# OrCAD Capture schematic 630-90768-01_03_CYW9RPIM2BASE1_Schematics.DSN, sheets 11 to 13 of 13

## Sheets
11 11. Power Supply & Accessories: size B
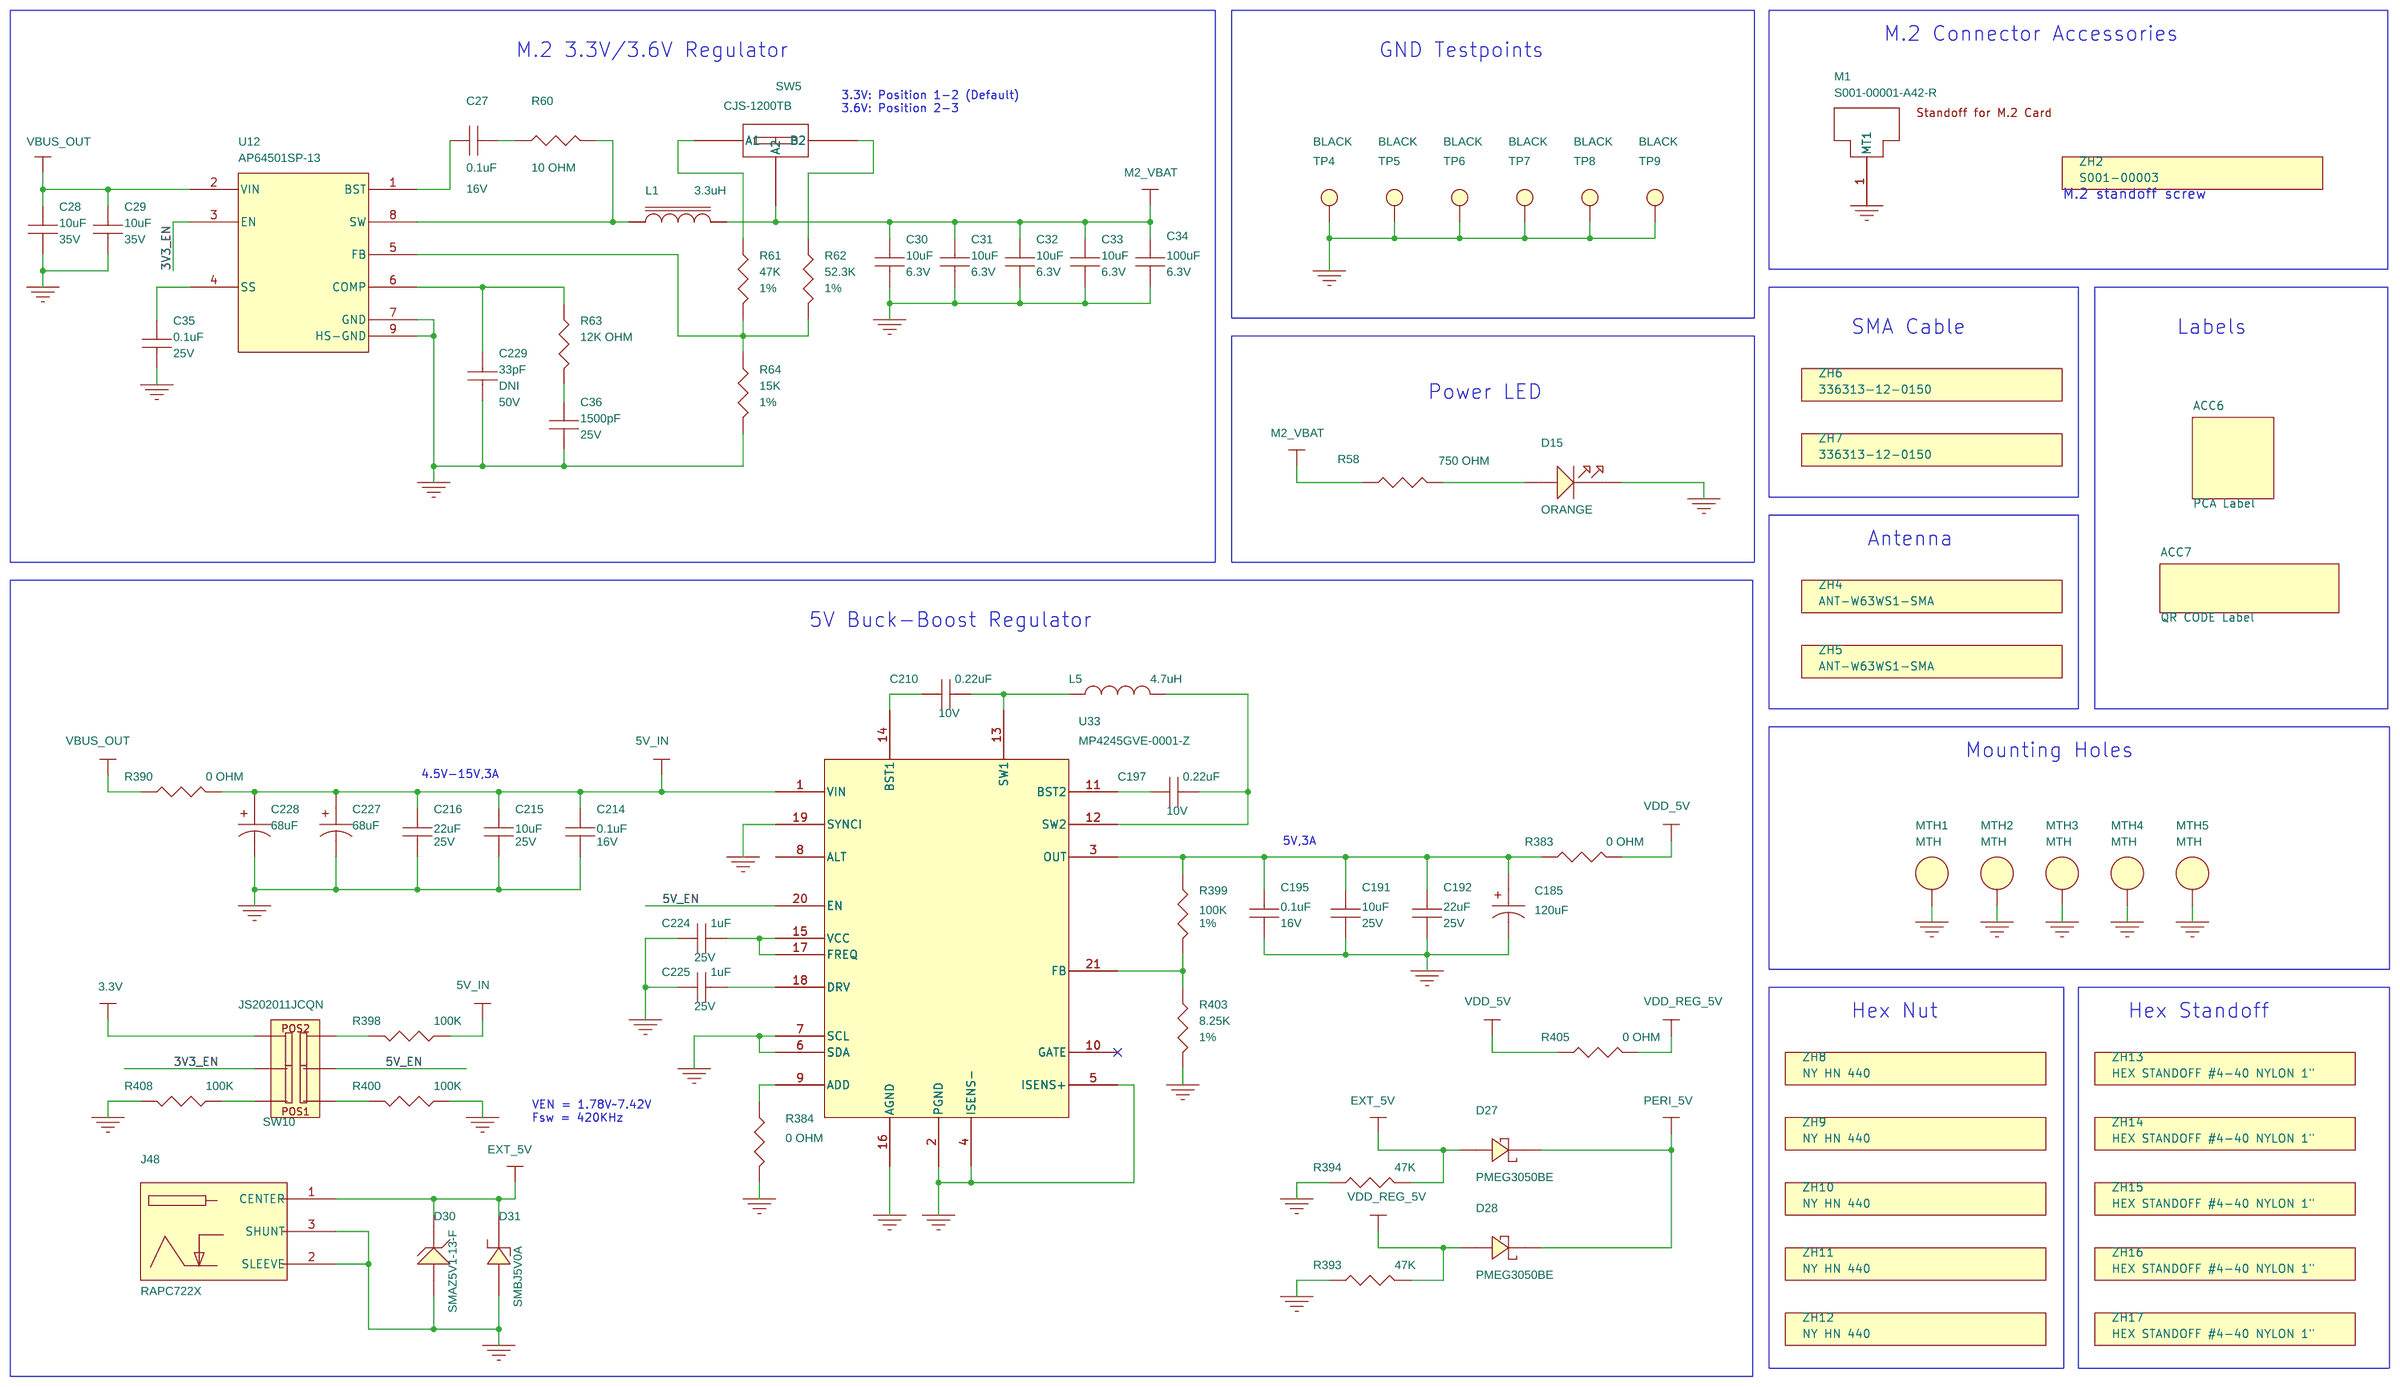
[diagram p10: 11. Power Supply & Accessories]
12 13. Revision History
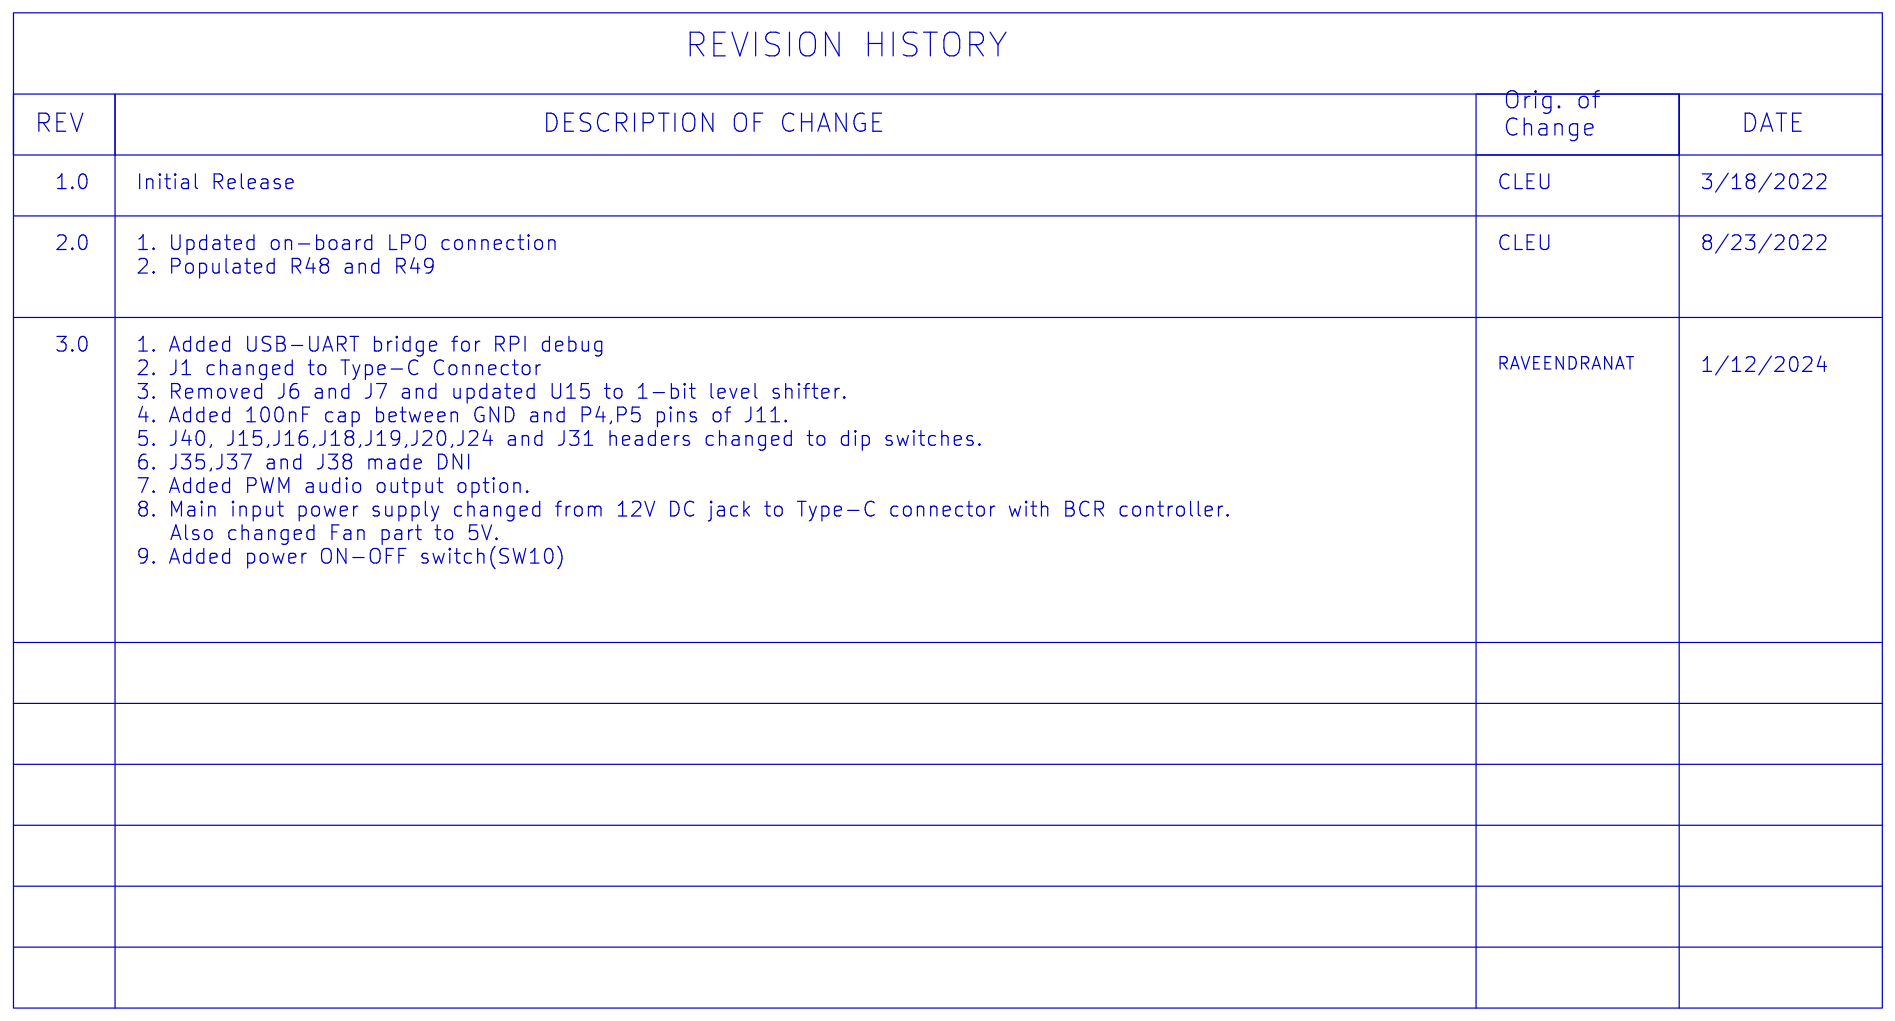
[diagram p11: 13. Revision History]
13 12. GPIO Mappings and Config.
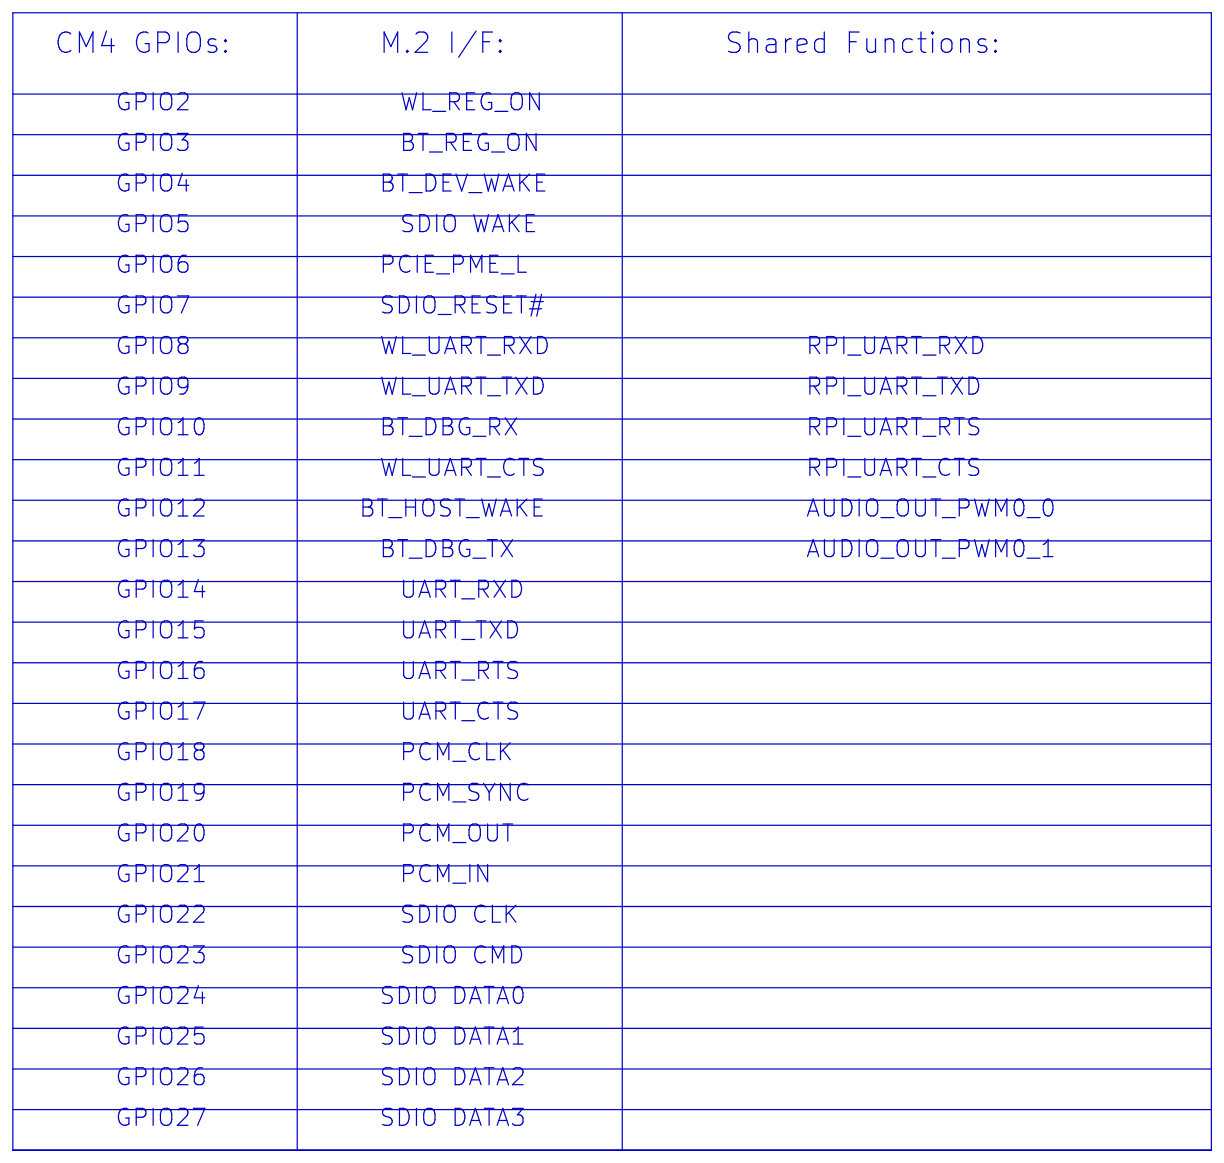
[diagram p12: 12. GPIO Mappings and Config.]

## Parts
ACC6  PCA Label  [TBD]
ACC7  QR CODE Label  [TBD]
C27  0.1uF  [CAPC1005_IS0402Q]
C28  10uF  [CAPC2012_IS0805Q]
C29  10uF  [CAPC2012_IS0805Q]
C30  10uF  [CAPC1005_IS0402Q]
C31  10uF  [CAPC1005_IS0402Q]
C32  10uF  [CAPC1005_IS0402Q]
C33  10uF  [CAPC1005_IS0402Q]
C34  100uF  [CAPC3216_IS1206N]
C35  0.1uF  [CAPC1608_IS0603Q]
C36  1500pF  [CAPC1005_IS0402Q]
C185  120uF  [CAPAE650X600N]
C191  10uF  [CAPC2012_IS0805Q]
C192  22uF  [CAPC2012_IS0805Q]
C195  0.1uF  [CAPC1005_IS0402Q]
C197  0.22uF  [CAPC1005_IS0402Q]
C210  0.22uF  [CAPC1005_IS0402Q]
C214  0.1uF  [CAPC1005_IS0402Q]
C215  10uF  [CAPC2012_IS0805Q]
C216  22uF  [CAPC2012_IS0805Q]
C224  1uF  [CAPC1608_IS0603Q]
C225  1uF  [CAPC1608_IS0603Q]
C227  68uF  [CAPAE650X600N]
C228  68uF  [CAPAE650X600N]
C229  33pF  [CAPC1005_IS0402Q]
D15  ORANGE  [LEDC1608Q]
D27  PMEG3050BE  [SODFL4725X110N]
D28  PMEG3050BE  [SODFL4725X110N]
D30  SMAZ5V1-13-F  [DIOM4326_SMA_DO214ACN]
D31  SMBJ5V0A  [DIOM4336_SMB_DO214AAN]
J48  RAPC722X  [SWCFT_RAPC722]
L1  3.3uH  [inds2_4p7mm_6x6]
L5  4.7uH  [IND_744311470]
M1  S001-00001-A42-R  [MT_pth4_20]
MTH1  MTH  [mtghole_tc650d350p]
MTH2  MTH  [mtghole_tc650d350p]
MTH3  MTH  [mtghole_tc650d350p]
MTH4  MTH  [mtghole_tc650d350p]
MTH5  MTH  [mtghole_tc650d350p]
R58  750 OHM  [RESC1005_IS0402Q]
R60  10 OHM  [RESC1005_IS0402Q]
R61  47K  [RESC1005_IS0402Q]
R62  52.3K  [RESC1005_IS0402Q]
R63  12K OHM  [RESC1005_IS0402Q]
R64  15K  [RESC1005_IS0402Q]
R383  0 OHM  [RESC2012_IS0805Q]
R384  0 OHM  [RESC1005_IS0402Q]
R390  0 OHM  [RESC2012_IS0805Q]
R393  47K  [RESC1005_IS0402Q]
R394  47K  [RESC1005_IS0402Q]
R398  100K  [RESC1005_IS0402Q]
R399  100K  [RESC1005_IS0402Q]
R400  100K  [RESC1005_IS0402Q]
R403  8.25K  [RESC1005_IS0402Q]
R405  0 OHM  [RESC2012_IS0805Q]
R408  100K  [RESC1005_IS0402Q]
SW5  CJS-1200TB  [SWDPS2_CJS]
SW10  JS202011JCQN  [SW_JS202011JCQN]
TP4  BLACK  [TPT1_KOB_151-10X-RC]
TP5  BLACK  [TPT1_KOB_151-10X-RC]
TP6  BLACK  [TPT1_KOB_151-10X-RC]
TP7  BLACK  [TPT1_KOB_151-10X-RC]
TP8  BLACK  [TPT1_KOB_151-10X-RC]
TP9  BLACK  [TPT1_KOB_151-10X-RC]
U12  AP64501SP-13  [so8_p127_490x600]
U33  MP4245GVE-0001-Z  [QFN50P400X500X100-21N_NOFID]
ZH2  S001-00003  [NA]
ZH4  ANT-W63WS1-SMA  [NA]
ZH5  ANT-W63WS1-SMA  [NA]
ZH6  336313-12-0150  [NA]
ZH7  336313-12-0150  [NA]
ZH8  NY HN 440  [NA]
ZH9  NY HN 440  [NA]
ZH10  NY HN 440  [NA]
ZH11  NY HN 440  [NA]
ZH12  NY HN 440  [NA]
ZH13  HEX STANDOFF #4-40 NYLON 1"  [NA]
ZH14  HEX STANDOFF #4-40 NYLON 1"  [NA]
ZH15  HEX STANDOFF #4-40 NYLON 1"  [NA]
ZH16  HEX STANDOFF #4-40 NYLON 1"  [NA]
ZH17  HEX STANDOFF #4-40 NYLON 1"  [NA]

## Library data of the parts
ACC6 = LABEL: LBL, PCA Label, Vendor Code, Datecode, Serial Number (YYWWVVXXXXX); CY_PN: 899-90120-01; Device File: 899-60120-01; HARD_LOCATION: YES; Manufacturer: JETech; Manufacturer_PN: 899-60120-01; Operating_Temp: NA; Part_Status: In Prod
ACC7 = Zero_Pin_Rect: LBL, QR CODE, 10mm X 10mm, CYW9RPIWIFIBT-EVK; CY_PN: 899-90258-01; HARD_LOCATION: YES; Manufacturer: Cypress Approved CM; Manufacturer_PN: NA; Operating_Temp: NA; Part_Status: Unrel
C27 C195 C214 = CAP: CAP, CER, 0402, 0.1uF, 10%, 16V, X7R; Assembly Instructions: <Assembly Instructions>; BRCM PN: 520157-00; CYPN: 510-90749-01; Enviromental: RoHS; FPLIST: CAPC1005_IS0402Q,CAPC1005_IS0402N,capc1005_is0402q_HP; PART TYPE: Ceramic Capacitor; Size: 0402; Status: APPROVED; TC: X7R; Tolerance: 10%; VOLTAGE: 16V; vendor_1: DARFON; vendor_2: DARFON; vendor_3: Walsin; vendor_4: Samsung; vendor_5: Murata Electronics North America; vendor_part_number_1: C1005X7R104KETS; vendor_part_number_2: C1005X7R104KETA; vendor_part_number_3: 0402B104K160CT; vendor_part_number_4: CL05B104KO5NNNC; vendor_part_number_5: GRM155R71C104KA88D -NRND-; Datasheet: \\shasdv005.infineon.com\CMU\CMU_ORCAD_CIS_LIB\CYPRESS_CIS_DATABASE\datasheet\Murata_GRM155R71C104KA88D.pdf
C28 C29 = CAP: CAP, CER, 0805, 10uF, 10%, 35V, X5R; Assembly Instructions: <Assembly Instructions>; CYPN: 510-91233-01; Enviromental: RoHS; FPLIST: CAPC2012_IS0805Q,CAPC2012_IS0805N; PART TYPE: Ceramic Capacitor; Size: 0805; Status: APPROVED; TC: X5R; Tolerance: 10%; VOLTAGE: 35V; vendor_1: Murata; vendor_part_number_1: GRM21BR6YA106KE43L; Datasheet: \\shasdv005.infineon.com\CMU\CMU_ORCAD_CIS_LIB\CYPRESS_CIS_DATABASE\datasheet\GRM21BR6YA106KE43L.pdf
C30-C33 = CAP: CAP, CER, 0402, 10uF, 20%, 6.3V, X5R; Assembly Instructions: <Assembly Instructions>; BRCM PN: 543921-00; CYPN: 510-90758-01; Enviromental: RoHS; FPLIST: CAPC1005_IS0402Q,CAPC1005_IS0402N; PART TYPE: Ceramic Capacitor; Size: 0402; Status: APPROVED; TC: X5R; Tolerance: 20%; VOLTAGE: 6.3V; vendor_1: DARFON; vendor_2: Murata; vendor_3: Murata; vendor_4: Walsin; vendor_part_number_1: C1005X5R106MCTS; vendor_part_number_2: GRM155R60J106ME44D-EOL; vendor_part_number_3: GRM155R60J106ME15D; vendor_part_number_4: 0402X106M6R3CT; Datasheet: \\shasdv005.infineon.com\CMU\CMU_ORCAD_CIS_LIB\CYPRESS_CIS_DATABASE\datasheet\GRM155R60J106ME44D.pdf
C34 = CAP: CAP, CER, 1206, 100uF, 20%, 6.3V, X5R; Assembly Instructions: <Assembly Instructions>; BRCM PN: 537294-00; CYPN: 510-91191-01; Enviromental: RoHS; PART TYPE: Ceramic Capacitor; Size: 1206; Status: APPROVED; TC: X5R; Tolerance: 20%; VOLTAGE: 6.3V; vendor_1: DARFON; vendor_2: Murata; vendor_3: Walsin; vendor_part_number_1: C3216X5R107MCPS; vendor_part_number_2: GRM31CR60J107ME39K; vendor_part_number_3: 1206X107M6R3CT; Datasheet: \\shasdv005.infineon.com\CMU\CMU_ORCAD_CIS_LIB\CYPRESS_CIS_DATABASE\datasheet\GRM31CR60J107ME39K.pdf
C35 = CAP: CAP, CER, 0603, 0.1uF, 10%, 25V, X7R; Assembly Instructions: <Assembly Instructions>; BRCM PN: 539741-00; CYPN: 510-90880-01; Enviromental: RoHS; FPLIST: CAPC1608_IS0603Q,CAPC1608_IS0603N; PART TYPE: Ceramic Capacitor; Size: 0603; Status: APPROVED; TC: X7R; Tolerance: 10%; VOLTAGE: 25V; vendor_1: DARFON; vendor_2: Murata; vendor_3: Walsin; vendor_part_number_1: C1608X7R104KFTS; vendor_part_number_2: GRM188R71E104KA01D; vendor_part_number_3: 0603B104K250CT
C36 = CAP: CAP, CER, 0402, 1500pF, 10%, 25V, X7R; Assembly Instructions: <Assembly Instructions>; BRCM PN: 501057-00; CYPN: 510-91198-01; Enviromental: RoHS; FPLIST: CAPC1005_IS0402Q,CAPC1005_IS0402N; PART TYPE: Ceramic Capacitor; Size: 0402; Status: APPROVED; TC: X7R; Tolerance: 10%; VOLTAGE: 25V; vendor_1: DARFON; vendor_2: Walsin; vendor_part_number_1: C1005X7R152KFTS; vendor_part_number_2: 0402B152K250CT; Datasheet: \\shasdv005.infineon.com\CMU\CMU_ORCAD_CIS_LIB\CYPRESS_CIS_DATABASE\datasheet\0402B152K250CT.pdf
C185 = CAP-PN: CAP, ELC, ALUM POLY, 120uF, 20%, 10V, 18mOHM, SMD, 6.5x6.5x5.7mm, -55 to 105C; Assembly Instructions: <Assembly Instructions>; CYPN: 510-91443-01; Enviromental: RoHS; PART TYPE: ELC Capacitor; Status: APPROVED; Tolerance: 20%; VOLTAGE: 10V; vendor_1: Nichicon; vendor_part_number_1: RSA1A121MCN1GS; Datasheet: \\shasdv005.infineon.com\CMU\CMU_ORCAD_CIS_LIB\CYPRESS_CIS_DATABASE\datasheet\RSA1A121MCN1GS.pdf
C191 C215 = CAP: CAP, CER, 0805, 10uF, 10%, 25V, X5R; Assembly Instructions: <Assembly Instructions>; CYPN: 510-91157-01; Enviromental: RoHS; FPLIST: CAPC2012_IS0805Q,CAPC2012_IS0805N; PART TYPE: Ceramic Capacitor; Size: 0805; Status: APPROVED; TC: X5R; Tolerance: 10%; VOLTAGE: 25V; vendor_1: DARFON; vendor_2: Murata; vendor_3: Walsin; vendor_part_number_1: C2012X5R106KFTS; vendor_part_number_2: GRM21BR61E106KA73K; vendor_part_number_3: 0805X106K250CG; Datasheet: \\shasdv005.infineon.com\CMU\CMU_ORCAD_CIS_LIB\CYPRESS_CIS_DATABASE\datasheet\C2012X5R106KFTS.pdf
C192 C216 = CAP: CAP, CER, 0805, 22uF, 20%, 25V, X5R; Assembly Instructions: <Assembly Instructions>; CYPN: 510-91147-01; Enviromental: RoHS; FPLIST: CAPC2012_IS0805Q,CAPC2012_IS0805N; PART TYPE: Ceramic Capacitor; Size: 0805; Status: APPROVED; TC: X5R; Tolerance: 20%; VOLTAGE: 25V; vendor_1: DARFON; vendor_2: Murata; vendor_3: Walsin; vendor_part_number_1: C2012X5R226MFPS; vendor_part_number_2: GRM21BR61E226ME44L; vendor_part_number_3: 0805X226M250CT; Datasheet: \\shasdv005.infineon.com\CMU\CMU_ORCAD_CIS_LIB\CYPRESS_CIS_DATABASE\datasheet\GRM21BR61E226ME44L.pdf
C197 C210 = CAP: CAP, CER, 0402, 0.22uF, 10%, 10V, X5R; Assembly Instructions: <Assembly Instructions>; BRCM PN: 547543-00; CYPN: 510-90756-01; Enviromental: RoHS; FPLIST: CAPC1005_IS0402Q,CAPC1005_IS0402N; PART TYPE: Ceramic Capacitor; Size: 0402; Status: APPROVED; TC: X5R; Tolerance: 10%; VOLTAGE: 10V; vendor_1: DARFON; vendor_2: Murata Electronics North America; vendor_3: Walsin; vendor_part_number_1: C1005X5R224KDTS; vendor_part_number_2: GRM155R61A224KE19D; vendor_part_number_3: 0402X224K100CT; Datasheet: \\shasdv005.infineon.com\CMU\CMU_ORCAD_CIS_LIB\CYPRESS_CIS_DATABASE\datasheet\GRM155R61A224KE19D.pdf
C224 C225 = CAP: CAP, CER, 0603, 1uF, 20%, 25V, X5R; Assembly Instructions: <Assembly Instructions>; CYPN: 510-90762-01; Enviromental: RoHS; FPLIST: CAPC1608_IS0603Q,CAPC1608_IS0603N; PART TYPE: Ceramic Capacitor; Size: 0603; Status: APPROVED; TC: X5R; Tolerance: 20%; VOLTAGE: 25V; vendor_1: DARFON; vendor_2: Murata; vendor_3: Walsin; vendor_part_number_1: C1608X5R105MFTS; vendor_part_number_2: GRM188R61E105MAADD; vendor_part_number_3: 0603X105M250CT
C227 C228 = CAP-PN: CAP, ELC, ALUM POLY, 68uF, 25V, 20%, 30mOHM, SMD, 6.5x6.5x5.7mm, -55 to 105C; Assembly Instructions: <Assembly Instructions>; CYPN: 510-91442-01; Enviromental: RoHS; PART TYPE: ELC Capacitor; Status: APPROVED; Tolerance: 20%; VOLTAGE: 50V; vendor_1: Nichicon; vendor_part_number_1: RSS1E680MCN1GS; Datasheet: \\shasdv005.infineon.com\CMU\CMU_ORCAD_CIS_LIB\CYPRESS_CIS_DATABASE\datasheet\RSS1E680MCN1GS.pdf
C229 = CAP: CAP, CER, 0402, 33pF, 1%, 50V, C0G; Assembly Instructions: <Assembly Instructions>; CYPN: 510-91197-01; DNI: DNI; Enviromental: RoHS; FPLIST: CAPC1005_IS0402Q,CAPC1005_IS0402N; PART TYPE: Ceramic Capacitor; Size: 0402; Status: APPROVED; TC: C0G; Tolerance: 1%; VOLTAGE: 50V; vendor_1: DARFON; vendor_2: Murata; vendor_3: Walsin; vendor_part_number_1: C1005NP0330FGTS; vendor_part_number_2: GRM1555C1H330FA01D; vendor_part_number_3: 0402N330F500CT; Datasheet: \\shasdv005.infineon.com\CMU\CMU_ORCAD_CIS_LIB\CYPRESS_CIS_DATABASE\datasheet\C1005NP0330FGTS.pdf
D15 = DIO-LED: DIO, LED, 0603, 2.5V, 20mA, ORANGE; Assembly Instructions: <Assembly Instructions>; BRCM PN: 540318-00; CYPN: 534-90135-01; Current: 20mA; Enviromental: RoHS; PART TYPE: LED; Status: APPROVED; VOLTAGE: 2.5V; vendor_1: Kingbright; vendor_2: Kingbright; vendor_part_number_1: KPG-1608SEKC-T; vendor_part_number_2: APG1608SEKC/T; Datasheet: \\shasdv005.infineon.com\CMU\CMU_ORCAD_CIS_LIB\CYPRESS_CIS_DATABASE\datasheet\534-90135-01.pdf
D27 D28 = DIO-SCHOTTKY: DIO, SCHOTTKY, 30V, 5A, SOD128, AEC-Q101; Assembly Instructions: <Assembly Instructions>; Automotive: Automotive; CYPN: 530-90210-01; Current: 5A; Enviromental: RoHS; PART TYPE: SCHOTTKY; Status: APPROVED; VOLTAGE: 30V; vendor_1: Nexperia; vendor_part_number_1: PMEG3050BEP,115; Datasheet: \\shasdv005.infineon.com\CMU\CMU_ORCAD_CIS_LIB\CYPRESS_CIS_DATABASE\datasheet\PMEG3050BEP,115.pdf
D30 = DIO-ZENER: DIO, ZNR, SMA, 5.1V, 100mA, 1W; Assembly Instructions: <Assembly Instructions>; BRCM PN: 541051-00; CYPN: 530-90156-01; Current: 100mA; Enviromental: RoHS; PART TYPE: ZENER; Status: APPROVED; VOLTAGE: 5.1V; vendor_1: Diodes Inc; Datasheet: \\shasdv005.infineon.com\CMU\CMU_ORCAD_CIS_LIB\CYPRESS_CIS_DATABASE\datasheet\SMAZ5V1-13-F.pdf
D31 = DIO-TVS: DIO, TVS, SMB, 5VWM, 9.2VC, 65.2A, 600W; Assembly Instructions: <Assembly Instructions>; BRCM PN: 531657-00; CYPN: 530-90159-01; Current: 65.2A; Enviromental: RoHS; PART TYPE: TVS; Status: APPROVED; VOLTAGE: 9.2VC; vendor_1: Fairchild Semiconductor; vendor_2: Fairchild Semiconductor; vendor_part_number_1: SMBJ5V0A_NL; Datasheet: \\shasdv005.infineon.com\CMU\CMU_ORCAD_CIS_LIB\CYPRESS_CIS_DATABASE\datasheet\SMBJ5V0A.pdf
J48 = CON-CNTR-SLEV-SHNT-J: CON, POWER, JACK, M, T/H, R/A, 1PORT, 2mmID, 5.5mmOD, 3PIN; Assembly Instructions: <Assembly Instructions>; BRCM PN: 528297-00; CYPN: 720-90486-01; Enviromental: RoHS; PART TYPE: POWER; Status: APPROVED; vendor_1: SWITCHCRAFT; Datasheet: \\shasdv005.infineon.com\CMU\CMU_ORCAD_CIS_LIB\CYPRESS_CIS_DATABASE\datasheet\Switchcraft_DS_RAPC722X.pdf
L1 = IND-SHIELDED-NO-DOT: IND, PWR, 3.3uH, 30%, 5A, 21mOHM, Q=15, Semi-Shielded, 6.0x6.0x4.2MM, AUTO; Assembly Instructions: <Assembly Instructions>; Automotive: Automotive; CYPN: 520-90452-01; Enviromental: RoHS; PART TYPE: POWER; Status: APPROVED; Tolerance: 30%; vendor_1: Bourns Inc; vendor_part_number_1: SRN6045TA-3R3Y; Datasheet: \\shasdv005.infineon.com\CMU\CMU_ORCAD_CIS_LIB\CYPRESS_CIS_DATABASE\datasheet\srn6045ta.pdf
L5 = IND: IND, PWR, SHLD, HIGH CURRENT, 4.7uH, 20%, 6A, 19.5mOHM, SMD, 7.0X6.9X3.8mm, -40~150C, Critical; Assembly Instructions: <Assembly Instructions>; CYPN: 520-90488-01; Critical: CRITICAL; Enviromental: RoHS; PART TYPE: FIXED; Status: APPROVED; Tolerance: 20%; vendor_1: Wurth Elektronik Group; vendor_part_number_1: 744311470; Datasheet: \\shasdv005.infineon.com\CMU\CMU_ORCAD_CIS_LIB\CYPRESS_CIS_DATABASE\datasheet\744311470.pdf
M1 = SM3ZS067U410-NUT1-R1200: HW, NGFF STANDOFF, A TYPE, M3x0.5, 3.15mm LENGTH; CYPN: 702-90018-01; Enviromental: RoHS; PART TYPE: Standoff; Status: APPROVED; vendor_1: REGO; Datasheet: \\shasdv005.infineon.com\CMU\CMU_ORCAD_CIS_LIB\CYPRESS_CIS_DATABASE\datasheet\S001-00001-A42-R.pdf
MTH1-MTH5 = MTH: PCB Mounting Hole, 6.5MM PAD, 3.5MM DRILL; Assembly Instructions: <Assembly Instructions>; CYPN: 700-90168-01
R58 = RES: RES, THK, 0402, 750 OHM, 5%, 63mW; CYPN: 500-90957-01; Enviromental: RoHS; FPLIST: RESC1005_IS0402Q,RESC1005_IS0402N; PART TYPE: THICK FILM; Size: 0402; Status: APPROVED; Tolerance: 5%; vendor_1: CYNTEC; vendor_2: VIKING TECH; vendor_3: Walsin; vendor_part_number_1: PFR05S-751-JNH; vendor_part_number_2: CR-02JL6--750RAC; vendor_part_number_3: WR04X751 JTL
R60 = RES: RES, THK, 0402, 10 OHM, 5%, 63mW; Assembly Instructions: <Assembly Instructions>; CYPN: 500-91244-01; Enviromental: RoHS; FPLIST: RESC1005_IS0402Q,RESC1005_IS0402N; PART TYPE: THICK FILM; Size: 0402; Status: APPROVED; Tolerance: 5%; vendor_1: CYNTEC; vendor_2: VIKING TECH; vendor_3: Walsin; vendor_part_number_1: PFR05S-100-JNH; vendor_part_number_2: CR-02JL6---10RAC; vendor_part_number_3: WR04X100 JTL; Datasheet: \\shasdv005.infineon.com\CMU\CMU_ORCAD_CIS_LIB\CYPRESS_CIS_DATABASE\datasheet\PFR05S-100-JNH.pdf
R61 R393 R394 = RES: RES, THK, 0402, 47K OHM, 1%, 63mW; Assembly Instructions: <Assembly Instructions>; CYPN: 500-91281-01; Enviromental: RoHS; FPLIST: RESC1005_IS0402Q,RESC1005_IS0402N; PART TYPE: THICK FILM; Size: 0402; Status: APPROVED; Tolerance: 1%; vendor_1: Walsin; vendor_2: CYNTEC; vendor_3: VIKING TECH; vendor_part_number_1: WR04X4702FTL; vendor_part_number_2: PFR05S-473-FNH; vendor_part_number_3: CR-02FL6---47KAC; Datasheet: \\shasdv005.infineon.com\CMU\CMU_ORCAD_CIS_LIB\CYPRESS_CIS_DATABASE\datasheet\ASC_WR.pdf
R62 = RES: RES, THK, 0402, 52.3K OHM, 1%, 63mW; Assembly Instructions: <Assembly Instructions>; CYPN: 500-91282-01; Enviromental: RoHS; FPLIST: RESC1005_IS0402Q,RESC1005_IS0402N; PART TYPE: THICK FILM; Size: 0402; Status: APPROVED; Tolerance: 1%; vendor_1: CYNTEC; vendor_2: VIKING TECH; vendor_3: Walsin; vendor_part_number_1: PFR05S-5232-FNH; vendor_part_number_2: CR-02FL6--52K3AC; vendor_part_number_3: WR04X5232FTL; Datasheet: \\shasdv005.infineon.com\CMU\CMU_ORCAD_CIS_LIB\CYPRESS_CIS_DATABASE\datasheet\PFR05S-5232-FNH.pdf
R63 = RES: RES, THK, 0402, 12K OHM, 1%, 63mW; Assembly Instructions: <Assembly Instructions>; CYPN: 500-90852-01; Enviromental: RoHS; FPLIST: RESC1005_IS0402Q,RESC1005_IS0402N; PART TYPE: THICK FILM; Size: 0402; Status: APPROVED; Tolerance: 1%; vendor_1: CYNTEC; vendor_2: RALEC; vendor_3: VIKING TECH; vendor_4: Walsin; vendor_5: Yageo America; vendor_part_number_1: PFR05S-1202-FNH; vendor_part_number_2: RTT021202FTH; vendor_part_number_3: CR-02FL6---12KAC; vendor_part_number_4: WR04X1202FTL; vendor_part_number_5: RC0402FR-0712KL; Datasheet: \\shasdv005.infineon.com\CMU\CMU_ORCAD_CIS_LIB\CYPRESS_CIS_DATABASE\datasheet\CR REV.C3-160715.pdf
R64 = RES: RES, THK, 0402, 15K, 1%, 63mW; Assembly Instructions: <Assembly Instructions>; BRCM PN: 500477-00; CYPN: 500-91063-01; Enviromental: RoHS; FPLIST: RESC1005_IS0402Q,RESC1005_IS0402N; PART TYPE: THICK FILM; Size: 0402; Status: APPROVED; Tolerance: 1%; vendor_1: CYNTEC; vendor_2: KOA Speer Electronics; vendor_3: Panasonic-ECG; vendor_4: RALEC; vendor_5: VIKING TECH; vendor_6: Walsin; vendor_part_number_1: PFR05S-153-FNH; vendor_part_number_2: RK73H1ETQTP1502F; vendor_part_number_3: ERJ-2RKF153X; vendor_part_number_4: RTT021502FTH; vendor_part_number_5: CR-02FL6---15KAC; vendor_part_number_6: WR04X1502FTL; Datasheet: \\shasdv005.infineon.com\CMU\CMU_ORCAD_CIS_LIB\CYPRESS_CIS_DATABASE\datasheet\cr.pdf
R383 R390 R405 = RES: RES, THK, 0805, 0 OHM, 5%, 1/8W; Assembly Instructions: <Assembly Instructions>; BRCM PN: 500004-00; CYPN: 500-90979-01; Enviromental: RoHS; FPLIST: RESC2012_IS0805Q,RESC2012_IS0805N; PART TYPE: THICK FILM; Size: 0805; Status: APPROVED; Tolerance: 5%; vendor_1: Rohm Semiconductor; vendor_2: Walsin; vendor_3: Yageo America; vendor_4: VIKING TECH; vendor_part_number_1: MCR10EZPJ000; vendor_part_number_2: WR08X000PGL; vendor_part_number_3: RC0805JR-070RL; vendor_part_number_4: CR-05JL7----0RAC; Datasheet: \\shasdv005.infineon.com\CMU\CMU_ORCAD_CIS_LIB\CYPRESS_CIS_DATABASE\datasheet\Walsin_WR_resistor_ATCS01249-1.pdf
R384 = RES: RES, THK, 0402, 0 OHM, 63mW; Assembly Instructions: <Assembly Instructions>; BRCM PN: 500225-00; CYPN: 500-90842-01; Enviromental: RoHS; FPLIST: RESC1005_IS0402Q,RESC1005_IS0402N; PART TYPE: THICK FILM; Size: 0402; Status: APPROVED; Tolerance: 5%; vendor_1: Walsin; vendor_2: CYNTEC; vendor_3: KOA Speer Electronics; vendor_4: Panasonic-ECG; vendor_5: VIKING TECH; vendor_6: Yageo America; vendor_part_number_1: WR04X000 PTL; vendor_part_number_2: PFR05X-000-XNH; vendor_part_number_3: RK73Z1ETQTP; vendor_part_number_4: ERJ-2GE0R00X; vendor_part_number_5: CR-02JL6----0RAC; vendor_part_number_6: RC0402JR-070RL
R398-R400 R408 = RES: RES, THK, 0402, 100K, 1%, 63mW; Assembly Instructions: <Assembly Instructions>; BRCM PN: 500559-00; CYPN: 500-90994-01; Enviromental: RoHS; FPLIST: RESC1005_IS0402Q,RESC1005_IS0402N; PART TYPE: THICK FILM; Size: 0402; Status: APPROVED; Tolerance: 1%; vendor_1: CYNTEC; vendor_10: Walsin; vendor_11: Walsin; vendor_12: Yageo America; vendor_13: Yageo America; vendor_2: KOA Speer Electronics; vendor_3: Panasonic-ECG; vendor_4: RALEC; vendor_5: RALEC; vendor_6: RALEC; vendor_7: TA-I/TYEE; vendor_8: VIKING TECH; vendor_9: Walsin; vendor_part_number_1: PFR05S-104-FNH; vendor_part_number_10: WR04X1003FGL; vendor_part_number_11: WR04X1003FQL; vendor_part_number_12: RC0402FR-07100KL; vendor_part_number_13: RC0402FR-13100KL; vendor_part_number_2: RK73H1ETQTP1003F; vendor_part_number_3: ERJ-2RKF1003X; vendor_part_number_4: RTT021003FTE; vendor_part_number_5: RTT021003FTH; vendor_part_number_6: RTT021003FTP; vendor_part_number_7: RM04FTN1003; vendor_part_number_8: CR-02FL6--100KAC; vendor_part_number_9: WR04X1003FTL; Datasheet: \\shasdv005.infineon.com\CMU\CMU_ORCAD_CIS_LIB\CYPRESS_CIS_DATABASE\datasheet\ERJ-2RKF1003X.pdf
R403 = RES: RES, THK, 0402, 8.25K, 1%, 63mW, Tc=100; Assembly Instructions: <Assembly Instructions>; BRCM PN: 531149-00; CYPN: 500-91036-01; Enviromental: RoHS; FPLIST: RESC1005_IS0402Q,RESC1005_IS0402N; PART TYPE: THICK FILM; Size: 0402; Status: APPROVED; Tolerance: 1%; vendor_1: KOA Speer Electronics; vendor_2: Panasonic-ECG; vendor_3: VIKING TECH; vendor_4: Walsin; vendor_5: Yageo America; vendor_6: Yageo America; vendor_part_number_1: RK73H1ETTP8251F; vendor_part_number_2: ERJ-2RKF8251X; vendor_part_number_3: CR-02FL6--8K25AC; vendor_part_number_4: WR04X8251FTL; vendor_part_number_5: RC0402FR-078K25L; vendor_part_number_6: RC0402FR-138K25L; Datasheet: \\shasdv005.infineon.com\CMU\CMU_ORCAD_CIS_LIB\CYPRESS_CIS_DATABASE\datasheet\RK73H1ETTP8251F.pdf
SW5 = SW-DIP-1: SWH,DIP,SMT,STR,SPDT; Assembly Instructions: <Assembly Instructions>; CYPN: 770-90139-01; Enviromental: RoHS; PART TYPE: DIP; Status: APPROVED; vendor_1: Copal Electronics; Datasheet: \\shasdv005.infineon.com\CMU\CMU_ORCAD_CIS_LIB\CYPRESS_CIS_DATABASE\datasheet\CJS-1200TB.pdf
SW10 = SW_DPDT_JS202011CQN: SWITCH, SLIDE, DPDT, 300MA, 6V; Assembly Instructions: <Assembly Instructions>; CYPN: 770-90133-01; PART TYPE: SLIDE; vendor_1: C&K Components; Datasheet: \\shasdv005.infineon.com\CMU\CMU_ORCAD_CIS_LIB\CYPRESS_CIS_DATABASE\datasheet\JS202011JCQN.pdf
TP4-TP9 = TP: CON, TEST-POINT, T/H, STR, 1P, BLACK, BRONZE, ROUNDED TOP; BRCM PN: 530148-00; CYPN: 720-90454-01; Enviromental: RoHS; PART TYPE: THRU-HOLE; Status: APPROVED; vendor_1: Kobiconn; vendor_2: Keystone Electronics; vendor_3: PINGOOD ENTERPRISE CO.; vendor_part_number_1: 151-103-RC; vendor_part_number_2: 5006; vendor_part_number_3: JT-1P-CIB; Datasheet: \\shasdv005.infineon.com\CMU\CMU_ORCAD_CIS_LIB\CYPRESS_CIS_DATABASE\datasheet\530148-00M1-KOBI CONN.pdf
U12 = AP64501_SO-8EP: IC, Synchronous Buck Converter, Step-Down, DC/DC, 3.8/40V INPUT, 5A OUTPUT CURRENT, SO-8EP; Assembly Instructions: <Assembly Instructions>; CYPN: 450-90673-01; Enviromental: RoHS; PART TYPE: CONVERTER; Status: APPROVED; vendor_1: Diodes Inc; Datasheet: \\shasdv005.infineon.com\CMU\CMU_ORCAD_CIS_LIB\CYPRESS_CIS_DATABASE\datasheet\AP64501.pdf
U33 = MP4245_QFN21: IC, REG, BUCK-BOOST, ADJ, 4V-36V, 6A, 21PIN, QFN-21, -40 to 125C; Assembly Instructions: <Assembly Instructions>; CYPN: 450-90785-01; Enviromental: RoHS; PART TYPE: REG; Status: APPROVED; vendor_1: Monolithic Power Systems Inc; Datasheet: \\shasdv005.infineon.com\CMU\CMU_ORCAD_CIS_LIB\CYPRESS_CIS_DATABASE\datasheet\MP4245GVE-0001-Z.pdf
ZH2 = ZH: SCREW, FOR PCIE M2.0, PAN HEAD, M3X0.5, 3.7mm LENGTH, 4.5mm OUT DIA, STEEL; CYPN: 700-90162-01; Enviromental: RoHS; FPLIST: NA,HARDWARE; PART TYPE: SCREW; Status: APPROVED; vendor_1: REGO
ZH4 ZH5 = ZH: HARDWARE, WiFi 6 Blade-Style Antenna with SMA plug (male pin) connector; Assembly Instructions: <Assembly Instructions>; CYPN: 753-90021-01; Enviromental: RoHS; FPLIST: NA,HARDWARE; PART TYPE: Antenna; Status: APPROVED; vendor_1: Linx Tecnology; Datasheet: \\shasdv005.infineon.com\CMU\CMU_ORCAD_CIS_LIB\CYPRESS_CIS_DATABASE\datasheet\ant-w63ws1-ds.pdf
ZH6 ZH7 = ZH: CBL ASSY Coaxial U.FL (UMCC), AMC to SMA 1.13mm OD Coaxial Cable 5.906" (150.00mm); Assembly Instructions: <Assembly Instructions>; CYPN: 751-90036-01; Enviromental: RoHS; FPLIST: NA,HARDWARE; PART TYPE: Single Wire; Status: APPROVED; vendor_1: Amphenol; Datasheet: \\shasdv005.infineon.com\CMU\CMU_ORCAD_CIS_LIB\CYPRESS_CIS_DATABASE\datasheet\C336313-12-XXXX.pdf
ZH8-ZH12 = ZH: HW, HEX NUT , 1/4 inch, NYLON 4-40; Assembly Instructions: <Assembly Instructions>; CYPN: 704-90005-01; Enviromental: RoHS; FPLIST: NA,HARDWARE; PART TYPE: NUT; Status: APPROVED; vendor_1: B&F Fastners; Datasheet: \\shasdv005.infineon.com\CMU\CMU_ORCAD_CIS_LIB\CYPRESS_CIS_DATABASE\datasheet\Nylhexnut.pdf
ZH13-ZH17 = ZH: HW, STANDOFF, Threaded, #4-40, Nylon, 1.000" (25.40mm) 1", Natural; Assembly Instructions: <Assembly Instructions>; CYPN: 702-90025-01; Enviromental: RoHS; FPLIST: NA,HARDWARE; PART TYPE: Standoff; Status: APPROVED; vendor_1: Keystone Electronics; Datasheet: \\shasdv005.infineon.com\CMU\CMU_ORCAD_CIS_LIB\CYPRESS_CIS_DATABASE\datasheet\M65p74

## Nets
3.3V: SW10.3 ; also on sheet 1 7 8 9
3V3_EN: SW10.2 U12.3(EN)
5V_EN: SW10.6 U33.20(EN)
5V_IN: C214.1 C215.1 C216.1 C227.P C228.P R390.2 R398.1 U33.1(VIN)
GND: C28.2 C29.2 C30.2 C31.2 C32.2 C33.2 C34.2 C35.2 C36.2 C185.N C191.2 C192.2 C195.2 C214.2 C215.2 C216.2 C224.1 C225.1 C227.N C228.N C229.2 D15.C(CATHODE) D30.A(ANODE) D31.A(ANODE) J48.2(SLEEVE) J48.3(SHUNT) M1.1(MT1) MTH1.1(TP) MTH2.1(TP) MTH3.1(TP) MTH4.1(TP) MTH5.1(TP) R64.2 R384.1 R393.1 R394.1 R400.1 R403.2 R408.2 TP4.1(TP) TP5.1(TP) TP6.1(TP) TP7.1(TP) TP8.1(TP) TP9.1(TP) U12.7(GND) U12.9(HS-GND) U33.2(PGND) U33.4(ISENS-) U33.5(ISENS+) U33.6(SDA) U33.7(SCL) U33.16(AGND) U33.19(SYNCI) ; also on sheet 1 2 3 7 8 9 10
VBUS_OUT: C28.1 C29.1 R390.1 U12.2(VIN) ; also on sheet 1 2
VDD_5V: R383.2 R405.1 ; also on sheet 1 9
VDD_REG_5V: D28.A R393.2 R405.2
EXT_5V: D27.A D30.C(CATHODE) D31.C(CATHODE) J48.1(CENTER) R394.2
M2_VBAT: C30.1 C31.1 C32.1 C33.1 C34.1 L1.2 R58.1 SW5.2(A2) ; also on sheet 8 10
PERI_5V: D27.C D28.C ; also on sheet 7 8
N17504773: D15.A(ANODE) R58.2
N17512684: R61.2 R62.2 R64.1 U12.5(FB)
N17512777: C35.1 U12.4(SS)
N17512799: C27.1 U12.1(BST)
N17512803: C27.2 R60.1
N17512813: L1.1 R60.2 U12.8(SW)
N17512829: C229.1 R63.1 U12.6(COMP)
N17573256: R62.1 SW5.3(B2)
N17711071: R61.1 SW5.1(A1)
N17763457: C210.1 U33.14(BST1)
N17763461: C210.2 L5.1 U33.13(SW1)
N17763467: C197.2 L5.2 U33.12(SW2)
N17763564: C197.1 U33.11(BST2)
N17763650: C185.P C191.1 C192.1 C195.1 R383.1 R399.1 U33.3(OUT)
N17763766: C224.2 U33.15(VCC) U33.17(FREQ)
N17763790: R399.2 R403.1 U33.21(FB)
N17763820: C225.2 U33.18(DRV)
N17763850: R384.2 U33.9(ADD)
N17848252: R408.1 SW10.1
N17848257: R400.2 SW10.5
N17849598: R398.2 SW10.7
N17880549: C36.1 R63.2

Not connected (* = marked no-connect by the designer): U33 8(ALT) 10(GATE)*

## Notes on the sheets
sheet 11
- M.2 Connector Accessories
- M.2 3.3V/3.6V Regulator
- GND Testpoints
- 3.3V: Position 1-2 (Default)
  3.6V: Position 2-3
- M.2 standoff screw
- SMA Cable
- Labels
- Power LED
- Antenna
- 5V Buck-Boost Regulator
- Mounting Holes
- 4.5V-15V,3A
- 5V,3A
- Hex Nut
- Hex Standoff
- VEN = 1.78V~7.42V
  Fsw = 420KHz
sheet 12
- REVISION HISTORY
- Orig. of
  Change
- REV
- DESCRIPTION OF CHANGE
- DATE
- 1.0
- Initial Release
- CLEU
- 3/18/2022
- 2.0
- 1. Updated on-board LPO connection
  2. Populated R48 and R49
- CLEU
- 8/23/2022
- 3.0
- 1. Added USB-UART bridge for RPI debug
  2. J1 changed to Type-C Connector
  3. Removed J6 and J7 and updated U15 to 1-bit level shifter.
  4. Added 100nF cap between GND and P4,P5 pins of J11.
  5. J40, J15,J16,J18,J19,J20,J24 and J31 headers changed to dip switches.
  6. J35,J37 and J38 made DNI
  7. Added PWM audio output option.
  8. Main input power supply changed from 12V DC jack to Type-C connector with BCR controller.
     Also changed Fan part to 5V.
  9. Added power ON-OFF switch(SW10)
- RAVEENDRANAT
- 1/12/2024
sheet 13
- CM4 GPIOs:
- M.2 I/F:
- Shared Functions:
- GPIO2
- WL_REG_ON
- GPIO3
- BT_REG_ON
- GPIO4
- BT_DEV_WAKE
- GPIO5
- SDIO WAKE
- GPIO6
- PCIE_PME_L
- GPIO7
- SDIO_RESET#
- GPIO8
- WL_UART_RXD
- RPI_UART_RXD
- GPIO9
- WL_UART_TXD
- RPI_UART_TXD
- GPIO10
- BT_DBG_RX
- RPI_UART_RTS
- GPIO11
- WL_UART_CTS
- RPI_UART_CTS
- GPIO12
- BT_HOST_WAKE
- AUDIO_OUT_PWM0_0
- GPIO13
- BT_DBG_TX
- AUDIO_OUT_PWM0_1
- GPIO14
- UART_RXD
- GPIO15
- UART_TXD
- GPIO16
- UART_RTS
- GPIO17
- UART_CTS
- GPIO18
- PCM_CLK
- GPIO19
- PCM_SYNC
- GPIO20
- PCM_OUT
- GPIO21
- PCM_IN
- GPIO22
- SDIO CLK
- GPIO23
- SDIO CMD
- GPIO24
- SDIO DATA0
- GPIO25
- SDIO DATA1
- GPIO26
- SDIO DATA2
- GPIO27
- SDIO DATA3
